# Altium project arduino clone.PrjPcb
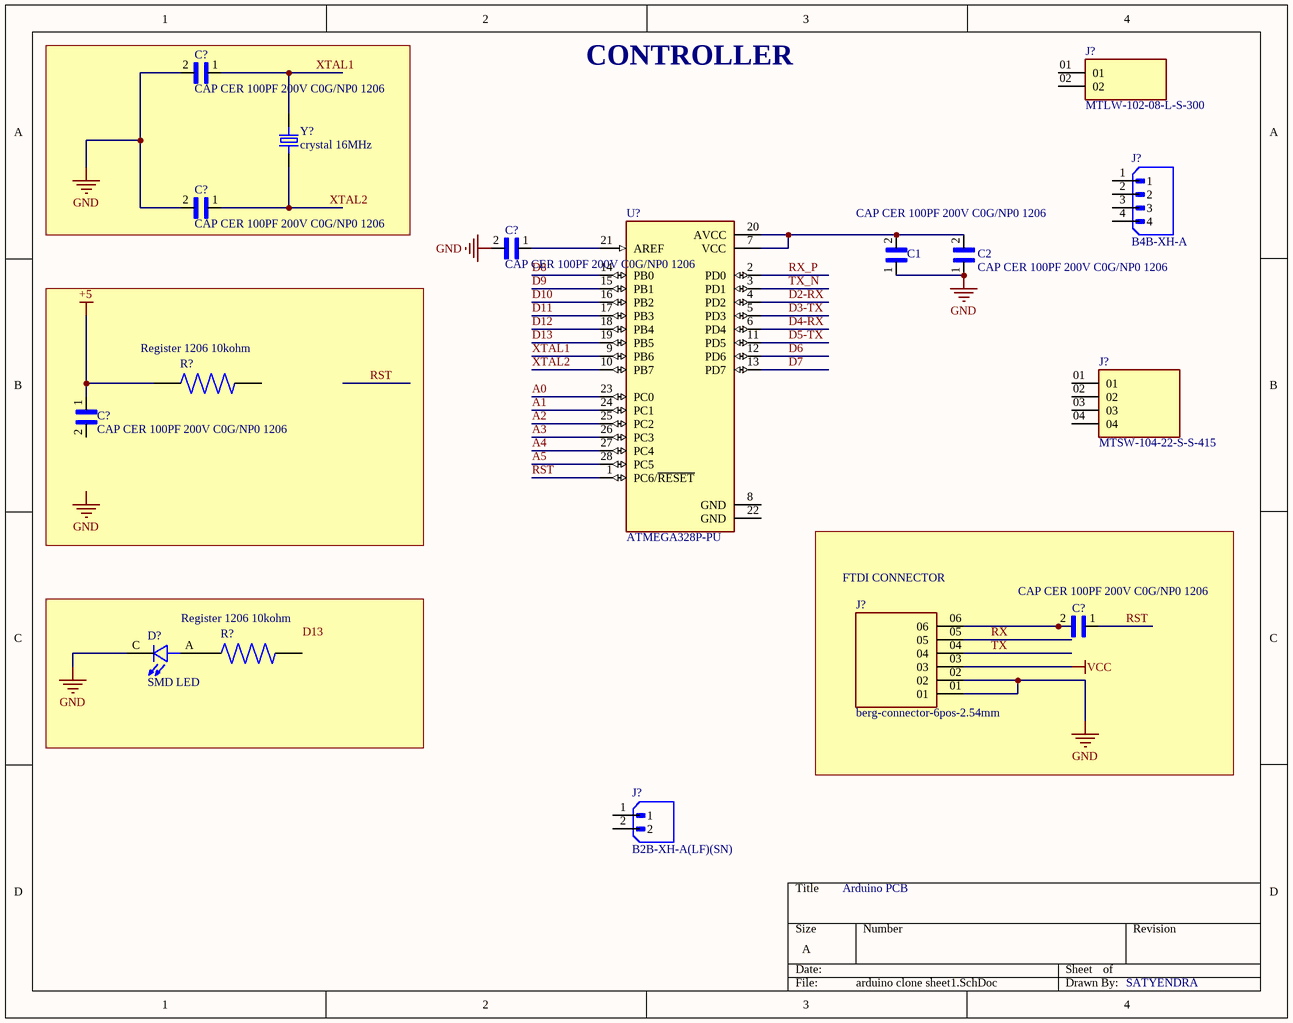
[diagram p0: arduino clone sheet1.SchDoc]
2 sheets, 19 parts. Net scope: global (net labels, ports and power ports of the same name join across sheets).
Board file: arduino clone PCB.PcbDoc
Sheets:
  arduino clone sheet1.SchDoc
  arduino clone sheet2.SchDoc

## Sheet arduino clone sheet1.SchDoc
size A; SheetNumber: 1; SheetTotal: 2

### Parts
(Parts that share a designator on the sheet are numbered #1, #2 ... from top to bottom, then left to right.)
C1  CAP CER 100PF 200V C0G/NP0 1206  [CAPC3216X88N]
C2  CAP CER 100PF 200V C0G/NP0 1206  [CAPC3216X88N]
C?#1  CAP CER 100PF 200V C0G/NP0 1206  [CAPC3216X88N]
C?#2  CAP CER 100PF 200V C0G/NP0 1206  [CAPC3216X88N]
C?#3  CAP CER 100PF 200V C0G/NP0 1206  [CAPC3216X88N]
C?#4  CAP CER 100PF 200V C0G/NP0 1206  [CAPC3216X88N]
C?#5  CAP CER 100PF 200V C0G/NP0 1206  [CAPC3216X88N]
D?#1  SMD LED  [LED_BR1102W-TR]
J?#1  MTLW-102-08-L-S-300  [SAMTEC_MTLW-102-08-L-S-300]
J?#2  B4B-XH-A  [JST_B4B-XH-A]
J?#3  MTSW-104-22-S-S-415  [SAMTEC_MTSW-104-22-S-S-415]
J?#4  berg-connector-6pos-2.54mm  [SAMTEC_SSQ-106-02-G-S-LL]
J?#5  B2B-XH-A(LF)(SN)  [JST_B2B-XH-A(LF)(SN)]
R?#1  Register 1206 10kohm  [RESC3015X65N]
R?#2  Register 1206 10kohm  [RESC3015X65N]
U?  ATMEGA328P-PU  [DIP794W46P254L2967H457Q28B]
Y?  crystal 16MHz  [XTAL_ECS-160-20-5PX-TR]

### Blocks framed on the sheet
FTDI CONNECTOR: C?#5 J?#4

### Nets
+5: C?#4.1 R?#1.1
GND: C1.1 C2.1 C?#1.2 C?#2.2 C?#3.2 D?#1.C J?#4.01 J?#4.02
VCC: J?#4.03
A0: U?.23(PC0)
A1: U?.24(PC1)
A2: U?.25(PC2)
A3: U?.26(PC3)
A4: U?.27(PC4)
A5: U?.28(PC5)
D2-RX: U?.4(PD2)
D3-TX: U?.5(PD3)
D4-RX: U?.6(PD4)
D5-TX: U?.11(PD5)
D6: U?.12(PD6)
D7: U?.13(PD7)
D8: U?.14(PB0)
D9: U?.15(PB1)
D10: U?.16(PB2)
D11: U?.17(PB3)
D12: U?.18(PB4)
D13: U?.19(PB5)
RST: C?#5.1 U?.1(PC6/~{RESET})
RX: J?#4.05
RX_P: U?.2(PD0)
TX: J?#4.04
TX_N: U?.3(PD1)
XTAL1: C?#1.1 U?.9(PB6) Y?.2
XTAL2: C?#2.1 U?.10(PB7) Y?.1
NetC1_2: C1.2 C2.2 U?.7(VCC) U?.20(AVCC)
NetC?#3_1: C?#3.1 U?.21(AREF)
NetC?#5_2: C?#5.2 J?#4.06
NetD?#1_A: D?#1.A R?#2.1

Not connected (* = marked no-connect by the designer): C?#4 2; J?#1 01 02; J?#2 1 2 3 4; J?#3 01 02 03 04; J?#5 1 2; R?#1 2; R?#2 2; U? 8(GND) 22(GND)

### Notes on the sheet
- CONTROLLER
- Arduino PCB
- SATYENDRA
- Labels drawn without touching a wire or pin: D13, GND

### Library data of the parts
C1 C2 C?#1-C?#5 = C1206C101J2GACTU
D?#1 = BR1102W-TR: LED Uni-Color Red 660nm 2-Pin SMD T/R
J?#2 = B4B-XH-A: Connector Header Through Hole 4 position 0.098 (2.50mm); MF: JST Sales
J?#4 = berg-connector-6pos-2.54mm: MF: Samtec; MP: SSQ-106-02-G-S-LL
J?#5 = B2B-XH-A(LF)(SN): Connector Header Through Hole 2 position 0.098 (2.50mm); MF: JST Sales
R?#1 R?#2 = Register 1206 10kohm: MP: RNCF1206BKY10K0
U? = ATMEGA328P-PU: ATmega Series 20 MHz 32 KB Flash 2 KB SRAM 8-Bit Microcontroller - DIP-28
Y? = ECS-160-20-5PX-TR: 16 MHz Â±30ppm Crystal 20pF 40 Ohms HC-49/US; MF: ECS Inc.

## Sheet arduino clone sheet2.SchDoc
size A; SheetNumber: 2; SheetTotal: 2
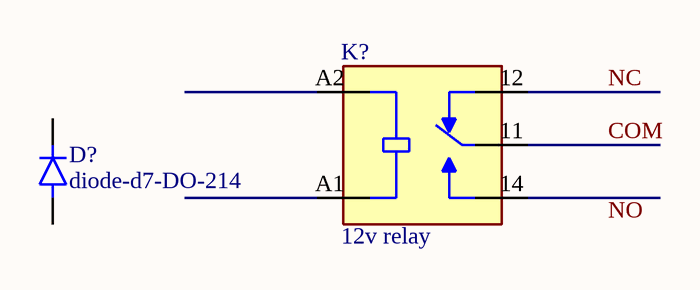
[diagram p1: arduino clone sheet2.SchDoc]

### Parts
(Parts that share a designator on the sheet are numbered #1, #2 ... from top to bottom, then left to right.)
D?#2  diode-d7-DO-214  [diode-d7-DO-214]
K?  12v relay  [RELAY_833H-1C-S-12VDC]

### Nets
COM: K?.11(COM)
NC: K?.12(NC)

Not connected (* = marked no-connect by the designer): D?#2 A C; K? 14(NO) A1(COIL2) A2(COIL1)

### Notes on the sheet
- Labels drawn without touching a wire or pin: NO

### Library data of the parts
D?#2 = diode-d7-DO-214: MF: Diodes Inc.; MP: S1M-13-F
K? = 833H-1C-S-12VDC: 833H Series 10 A SPDT 12 VDC Through Hole Miniature Sugar Cube Power Relay; MF: Song Chuan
